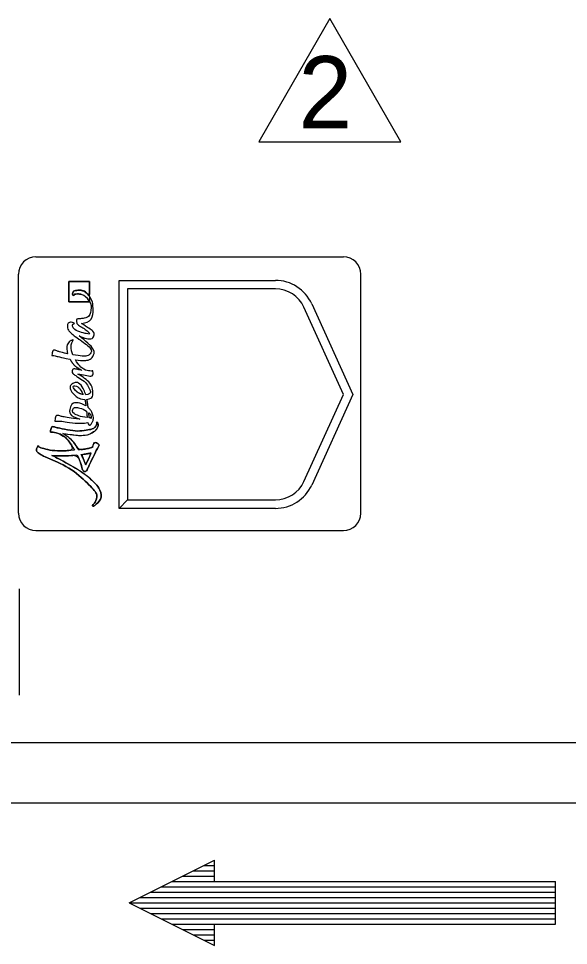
# Model space of a CAD drawing. Extents: x 1806 to 2022, y 110 to 389.
# Drawn here: x 1941.53 to 1952.54, y 222.97 to 241.53 of the extents above; entities that cross this region are included whole.
import ezdxf

# ---------------------------------------------------------------- set-up
doc = ezdxf.new("R2010")
doc.units = 0
for name, color, linetype in [('Level 10', 7, 'Continuous'), ('Level 2', 7, 'Continuous'), ('Level 44', 7, 'Continuous'), ('Level 50', 7, 'Continuous'), ('Level 53', 7, 'Continuous'), ('Level 60', 7, 'Continuous')]:
    doc.layers.add(name, color=color, linetype=linetype)

msp = doc.modelspace()

# ---------------------------------------------------------------- linework, layer by layer
at = {"layer": 'Level 10'}
for p, q in [((1957.331, 227.026), (1895.86, 227.026)), ((1957.331, 225.815), (1895.86, 225.815))]:
    msp.add_line(p, q, dxfattribs=at)
at = {"layer": 'Level 2'}
for p, q in [((1941.879, 236.756), (1948.034, 236.756)), ((1941.532, 231.624), (1941.532, 236.409)), ((1941.532, 231.624), (1941.532, 236.409)), ((1943.545, 231.72), (1943.545, 236.285)), ((1943.545, 236.285), (1946.672, 236.285)), ((1948.381, 231.624), (1948.381, 236.409)), ((1946.672, 236.114), (1943.716, 236.114)), ((1943.716, 236.114), (1943.716, 231.891)), ((1948.037, 234.002), (1947.243, 235.746)), ((1947.399, 235.817), (1948.225, 234.002)), ((1947.243, 232.259), (1948.037, 234.002)), ((1948.225, 234.002), (1947.399, 232.188)), ((1943.545, 231.72), (1943.716, 231.891)), ((1943.716, 231.891), (1943.545, 231.72)), ((1943.716, 231.891), (1946.672, 231.891)), ((1946.672, 231.72), (1943.545, 231.72)), ((1941.879, 231.277), (1948.034, 231.277))]:
    msp.add_line(p, q, dxfattribs=at)
for centre, radius, start, end in [((1941.879, 236.409), 0.347, 90, 180), ((1948.034, 236.409), 0.347, 360, 90), ((1946.672, 235.486), 0.799, 24.4568, 90), ((1946.672, 235.486), 0.628, 24.4568, 90), ((1946.672, 232.519), 0.628, 270, 335.5432), ((1946.672, 232.519), 0.799, 270, 335.5432), ((1941.879, 231.624), 0.347, 180, 270), ((1948.034, 231.624), 0.347, 270, 360)]:
    msp.add_arc(centre, radius, start, end, dxfattribs=at)
at = {"layer": 'Level 44'}
msp.add_line((1941.553, 227.978), (1941.553, 230.111), dxfattribs=at)
at = {"layer": 'Level 50'}
for p, q in [((1943.747, 223.822), (1945.453, 224.675)), ((1945.24, 224.569), (1945.453, 224.569)), ((1945.453, 224.249), (1945.453, 224.675)), ((1945.027, 224.462), (1945.453, 224.462)), ((1944.6, 224.249), (1952.28, 224.249)), ((1944.813, 224.355), (1945.453, 224.355)), ((1945.453, 224.249), (1952.28, 224.249)), ((1952.28, 223.395), (1952.28, 224.249)), ((1944.173, 224.035), (1952.28, 224.035)), ((1944.387, 224.142), (1952.28, 224.142)), ((1943.747, 223.822), (1952.28, 223.822)), ((1943.747, 223.822), (1945.453, 222.969)), ((1943.96, 223.929), (1952.28, 223.929)), ((1943.96, 223.715), (1952.28, 223.715)), ((1944.173, 223.609), (1952.28, 223.609)), ((1944.387, 223.502), (1952.28, 223.502)), ((1944.6, 223.395), (1952.28, 223.395)), ((1944.813, 223.289), (1945.453, 223.289)), ((1945.453, 223.395), (1952.28, 223.395)), ((1945.453, 222.969), (1945.453, 223.395)), ((1945.027, 223.182), (1945.453, 223.182)), ((1945.24, 223.075), (1945.453, 223.075))]:
    msp.add_line(p, q, dxfattribs=at)
at = {"layer": 'Level 53'}
msp.add_line((1942.949, 235.965), (1942.949, 235.865), dxfattribs=at)
msp.add_lwpolyline([(1942.949, 235.965), (1942.949, 236.26), (1942.542, 236.26), (1942.542, 235.853), (1942.949, 235.853), (1942.949, 235.865)], dxfattribs=at)
for points, degree in [([(1942.542, 235.853), (1942.542, 235.853), (1942.949, 235.853), (1942.949, 235.853), (1942.949, 235.853), (1942.949, 235.865), (1942.949, 235.865), (1942.896, 235.953), (1942.795, 236.013), (1942.712, 236.013), (1942.64, 236.012), (1942.644, 235.974), (1942.634, 235.979), (1942.605, 235.991), (1942.621, 236.081), (1942.723, 236.086), (1942.809, 236.091), (1942.892, 236.046), (1942.949, 235.965), (1942.949, 235.965), (1942.949, 236.26), (1942.949, 236.26), (1942.949, 236.26), (1942.542, 236.26), (1942.542, 236.26), (1942.542, 236.26), (1942.542, 235.853), (1942.542, 235.853)], 3), ([(1942.949, 235.865), (1942.896, 235.953), (1942.795, 236.013), (1942.712, 236.013), (1942.64, 236.012), (1942.644, 235.974), (1942.634, 235.979), (1942.605, 235.991), (1942.621, 236.081), (1942.723, 236.086), (1942.809, 236.091), (1942.892, 236.046), (1942.949, 235.965)], 3), ([(1942.794, 235.422), (1942.878, 235.432), (1943.023, 235.488), (1943.023, 235.714), (1943.023, 235.815), (1942.995, 235.901), (1942.949, 235.965)], 3), ([(1942.985, 235.739), (1942.985, 235.572), (1942.856, 235.528), (1942.791, 235.52), (1942.748, 235.515), (1942.687, 235.524), (1942.695, 235.45), (1942.701, 235.399), (1942.801, 235.352), (1942.886, 235.286), (1942.959, 235.23), (1942.952, 235.205), (1942.889, 235.218), (1942.811, 235.234), (1942.628, 235.3), (1942.614, 235.374), (1942.608, 235.409), (1942.669, 235.421), (1942.631, 235.437), (1942.593, 235.453), (1942.511, 235.439), (1942.511, 235.361), (1942.511, 235.307), (1942.568, 235.242), (1942.633, 235.189), (1942.69, 235.142), (1943.036, 234.908), (1942.961, 234.809), (1942.926, 234.763), (1942.784, 234.767), (1942.617, 234.796)], 3), ([(1942.949, 235.865), (1942.972, 235.827), (1942.985, 235.784), (1942.985, 235.739)], 2), ([(1942.746, 235.175), (1942.863, 235.123), (1943.015, 235.093), (1943.038, 235.172), (1943.064, 235.264), (1942.912, 235.337), (1942.794, 235.422)], 3), ([(1942.669, 234.694), (1942.827, 234.676), (1942.968, 234.682), (1943.013, 234.754), (1943.095, 234.886), (1942.878, 235.072), (1942.746, 235.175)], 3), ([(1942.617, 234.796), (1942.572, 234.913), (1942.587, 235.01), (1942.613, 235.065), (1942.626, 235.092), (1942.624, 235.096), (1942.594, 235.084), (1942.55, 235.067), (1942.482, 234.973), (1942.513, 234.826), (1942.514, 234.823), (1942.515, 234.819), (1942.516, 234.816)], 3), ([(1942.516, 234.816), (1942.462, 234.828), (1942.406, 234.841), (1942.353, 234.856), (1942.304, 234.87), (1942.219, 234.91), (1942.202, 234.805), (1942.197, 234.772), (1942.213, 234.786), (1942.259, 234.775), (1942.342, 234.754), (1942.45, 234.729), (1942.559, 234.71)], 3), ([(1942.559, 234.71), (1942.609, 234.624), (1942.692, 234.543), (1942.802, 234.484)], 2), ([(1942.721, 234.409), (1942.819, 234.399), (1943.033, 234.336), (1943.022, 234.444), (1943.018, 234.487), (1943.011, 234.468), (1942.974, 234.471), (1942.845, 234.481), (1942.736, 234.588), (1942.669, 234.694)], 3), ([(1942.802, 234.484), (1942.751, 234.494), (1942.695, 234.51), (1942.658, 234.511), (1942.618, 234.512), (1942.609, 234.485), (1942.606, 234.475), (1942.599, 234.452), (1942.611, 234.424), (1942.65, 234.396), (1942.741, 234.332), (1942.884, 234.25), (1942.945, 234.126), (1942.988, 234.037), (1942.944, 233.998), (1942.877, 233.996)], 3), ([(1942.9, 233.901), (1942.972, 233.91), (1943.027, 233.956), (1943.017, 234.065), (1943.003, 234.22), (1942.813, 234.357), (1942.721, 234.409)], 3), ([(1942.877, 233.996), (1942.872, 234.013), (1942.866, 234.029), (1942.861, 234.042), (1942.789, 234.203), (1942.681, 234.259), (1942.616, 234.218), (1942.553, 234.179), (1942.572, 234.068), (1942.665, 233.98), (1942.71, 233.937), (1942.789, 233.903), (1942.86, 233.9)], 3), ([(1942.673, 234.082), (1942.623, 234.136), (1942.626, 234.163), (1942.64, 234.17), (1942.669, 234.185), (1942.772, 234.122), (1942.828, 234)], 3), ([(1942.828, 234), (1942.773, 234.01), (1942.712, 234.039), (1942.673, 234.082)], 2), ([(1942.882, 233.772), (1942.759, 233.847), (1942.593, 233.841), (1942.565, 233.73), (1942.532, 233.602), (1942.657, 233.537), (1942.761, 233.509)], 3), ([(1942.86, 233.9), (1942.868, 233.862), (1942.875, 233.82), (1942.882, 233.772)], 2), ([(1942.926, 233.739), (1942.919, 233.793), (1942.911, 233.849), (1942.9, 233.901)], 2), ([(1942.905, 233.537), (1942.774, 233.554), (1942.593, 233.622), (1942.622, 233.707), (1942.639, 233.755), (1942.792, 233.73), (1942.894, 233.667)], 3), ([(1942.894, 233.667), (1942.898, 233.626), (1942.902, 233.582), (1942.905, 233.537)], 2), ([(1942.917, 233.44), (1942.931, 233.394), (1942.966, 233.375), (1943.002, 233.434), (1943.027, 233.475), (1943.036, 233.564), (1942.991, 233.655), (1942.975, 233.687), (1942.953, 233.715), (1942.926, 233.739)], 3), ([(1942.761, 233.509), (1942.657, 233.518), (1942.53, 233.534), (1942.413, 233.558), (1942.364, 233.567), (1942.279, 233.601), (1942.262, 233.494), (1942.257, 233.461), (1942.273, 233.466), (1942.319, 233.469), (1942.38, 233.472), (1942.753, 233.404), (1942.917, 233.44)], 3), ([(1942.946, 233.533), (1942.945, 233.556), (1942.942, 233.592), (1942.938, 233.634)], 2), ([(1942.938, 233.634), (1942.963, 233.612), (1942.98, 233.587), (1942.984, 233.56)], 2), ([(1942.984, 233.523), (1942.979, 233.529), (1942.972, 233.532), (1942.963, 233.532), (1942.957, 233.532), (1942.952, 233.532), (1942.946, 233.533)], 3), ([(1942.984, 233.56), (1942.986, 233.545), (1942.986, 233.533), (1942.984, 233.523)], 2), ([(1943.097, 233.411), (1943.091, 233.367), (1943.031, 233.31), (1942.933, 233.293), (1942.756, 233.261), (1942.582, 233.28), (1942.323, 233.332), (1942.274, 233.341), (1942.189, 233.375), (1942.172, 233.268), (1942.167, 233.235), (1942.184, 233.252), (1942.229, 233.243), (1942.422, 233.202), (1942.561, 233.044), (1942.655, 232.885), (1942.433, 232.868), (1942.187, 232.875), (1942.037, 232.917), (1941.91, 232.952), (1941.933, 232.994), (1941.906, 232.942), (1941.878, 232.887), (1941.915, 232.829), (1942.01, 232.781), (1942.105, 232.734), (1942.619, 232.515), (1942.966, 232.166), (1943.144, 231.987), (1943.052, 231.826), (1943.025, 231.794), (1943.003, 231.767), (1943.037, 231.757), (1943.072, 231.79), (1943.228, 231.935), (1943.139, 232.146), (1943.062, 232.223), (1942.849, 232.435), (1942.392, 232.682), (1942.199, 232.782), (1942.308, 232.772), (1942.491, 232.769), (1942.705, 232.79), (1942.758, 232.682), (1942.789, 232.585), (1942.801, 232.539), (1942.814, 232.49), (1942.834, 232.459), (1942.857, 232.458), (1942.882, 232.457), (1942.904, 232.49), (1942.926, 232.538), (1942.967, 232.624), (1943.085, 232.874), (1943.121, 232.936), (1943.152, 232.989), (1943.128, 233.015), (1943.095, 233.03), (1943.052, 233.051), (1943.027, 232.995), (1943.01, 232.94), (1942.938, 232.92), (1942.84, 232.903), (1942.732, 232.892), (1942.654, 233.019), (1942.549, 233.145), (1942.419, 233.217), (1942.528, 233.199), (1942.899, 233.152), (1943.056, 233.269), (1943.09, 233.295), (1943.128, 233.352), (1943.122, 233.407), (1943.12, 233.433), (1943.103, 233.447), (1943.097, 233.444), (1943.092, 233.441), (1943.099, 233.426), (1943.097, 233.411)], 3), ([(1943.097, 233.411), (1943.091, 233.367), (1943.031, 233.31), (1942.933, 233.293), (1942.756, 233.261), (1942.582, 233.28), (1942.323, 233.332), (1942.274, 233.341), (1942.189, 233.375), (1942.172, 233.268), (1942.167, 233.235), (1942.184, 233.252), (1942.229, 233.243), (1942.422, 233.202), (1942.561, 233.044), (1942.655, 232.885)], 3), ([(1942.419, 233.217), (1942.528, 233.199), (1942.899, 233.152), (1943.056, 233.269), (1943.09, 233.295), (1943.128, 233.352), (1943.122, 233.407), (1943.12, 233.433), (1943.103, 233.447), (1943.097, 233.444), (1943.092, 233.441), (1943.099, 233.426), (1943.097, 233.411)], 3), ([(1942.732, 232.892), (1942.654, 233.019), (1942.549, 233.145), (1942.419, 233.217)], 2), ([(1942.655, 232.885), (1942.433, 232.868), (1942.187, 232.875), (1942.037, 232.917), (1941.91, 232.952), (1941.933, 232.994), (1941.906, 232.942), (1941.878, 232.887), (1941.915, 232.829), (1942.01, 232.781), (1942.105, 232.734), (1942.619, 232.515), (1942.966, 232.166), (1943.144, 231.987), (1943.052, 231.826), (1943.025, 231.794), (1943.003, 231.767), (1943.037, 231.757), (1943.072, 231.79), (1943.228, 231.935), (1943.139, 232.146), (1943.062, 232.223), (1942.849, 232.435), (1942.392, 232.682), (1942.199, 232.782)], 3), ([(1942.705, 232.79), (1942.758, 232.682), (1942.789, 232.585), (1942.801, 232.539), (1942.814, 232.49), (1942.834, 232.459), (1942.857, 232.458), (1942.882, 232.457), (1942.904, 232.49), (1942.926, 232.538), (1942.967, 232.624), (1943.085, 232.874), (1943.121, 232.936), (1943.152, 232.989), (1943.128, 233.015), (1943.095, 233.03), (1943.052, 233.051), (1943.027, 232.995), (1943.01, 232.94)], 3), ([(1943.01, 232.94), (1942.938, 232.92), (1942.84, 232.903), (1942.732, 232.892)], 2), ([(1942.199, 232.782), (1942.308, 232.772), (1942.491, 232.769), (1942.705, 232.79)], 2), ([(1942.785, 232.798), (1942.872, 232.808), (1942.934, 232.82), (1942.981, 232.832)], 2), ([(1942.876, 232.594), (1942.855, 232.651), (1942.825, 232.723), (1942.785, 232.798)], 2), ([(1942.876, 232.594), (1942.855, 232.651), (1942.825, 232.723), (1942.785, 232.798), (1942.872, 232.808), (1942.934, 232.82), (1942.981, 232.832), (1942.961, 232.776), (1942.928, 232.697), (1942.876, 232.594)], 3), ([(1942.981, 232.832), (1942.961, 232.776), (1942.928, 232.697), (1942.876, 232.594)], 2)]:
    msp.add_open_spline(points, degree=degree, dxfattribs=at)
at = {"layer": 'Level 60'}
for points in [[(1947.761, 241.528), (1946.368, 239.103)], [(1949.155, 239.103), (1947.761, 241.528)], [(1946.368, 239.103), (1946.342, 239.058), (1949.181, 239.058), (1949.155, 239.103)]]:
    msp.add_lwpolyline(points, dxfattribs=at)

# ---------------------------------------------------------------- texts
msp.add_text('2', height=1.448, rotation=360, dxfattribs=at).set_placement((1947.134, 239.327))

doc.saveas('drawing.dxf')
